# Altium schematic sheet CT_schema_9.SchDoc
size 254 x 194 mm
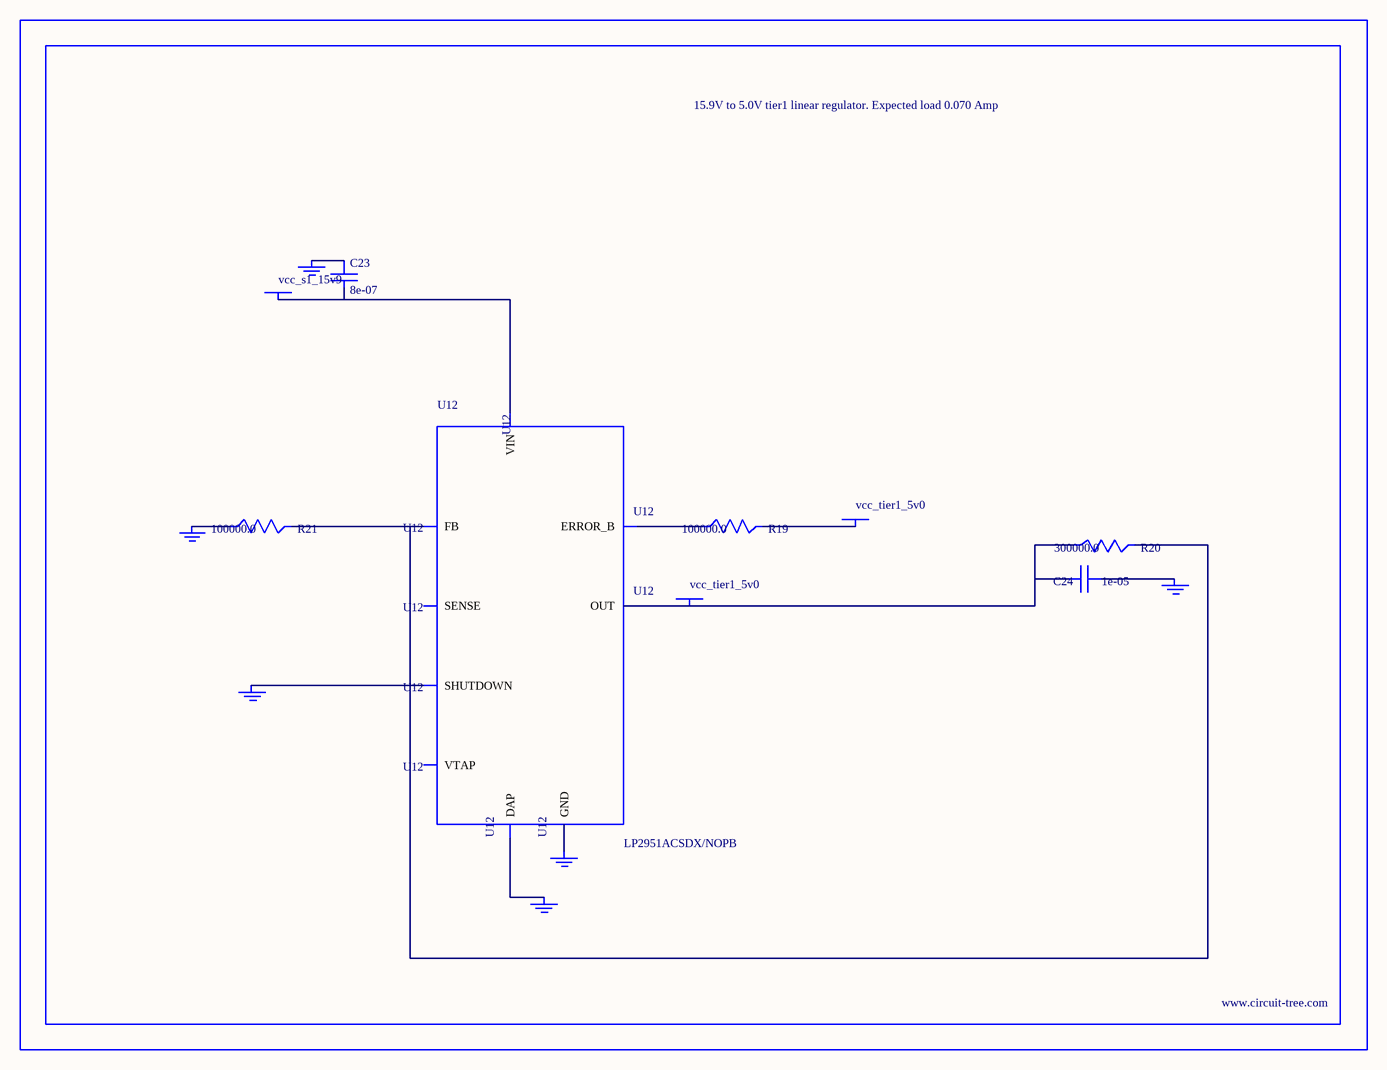
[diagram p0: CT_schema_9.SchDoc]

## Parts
BORDER8  (no value)
C23  8e-07  [R0603]
C24  1e-05  [C1210]
GND_INSTANCE_8_0  (no value)
GND_INSTANCE_8_1  (no value)
GND_INSTANCE_8_2  (no value)
GND_INSTANCE_8_3  (no value)
GND_INSTANCE_8_4  (no value)
GND_INSTANCE_8_5  (no value)
POWER_INSTANCE_8_0  vcc_tier1_5v0
POWER_INSTANCE_8_1  vcc_s1_15v9
POWER_INSTANCE_8_2  vcc_tier1_5v0
R19  100000.0  [R0603]
R20  300000.0  [R0603]
R21  100000.0  [R0603]
U12  LP2951ACSDX/NOPB  [WSON-8]

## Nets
NetC23_1: C23.1 GND_INSTANCE_8_3.0(GND)
NetC23_2: C23.2 POWER_INSTANCE_8_1.0(PWR) U12.8(VIN)
NetC24_1: C24.1 GND_INSTANCE_8_0.0(GND)
NetC24_2: C24.2 POWER_INSTANCE_8_2.0(PWR) R20.1 U12.1(OUT)
NetGND_INSTANCE_8_1_0: GND_INSTANCE_8_1.0(GND) U12.3(SHUTDOWN)
NetGND_INSTANCE_8_2_0: GND_INSTANCE_8_2.0(GND) R21.1
NetGND_INSTANCE_8_4_0: GND_INSTANCE_8_4.0(GND) U12.PAD(DAP)
NetGND_INSTANCE_8_5_0: GND_INSTANCE_8_5.0(GND) U12.4(GND)
NetPOWER_INSTANCE_8_0_0: POWER_INSTANCE_8_0.0(PWR) R19.2
NetR19_1: R19.1 U12.5(ERROR_B)
NetR20_2: R20.2 R21.2 U12.7(FB)

Not connected (* = marked no-connect by the designer): U12 2(SENSE) 6(VTAP)

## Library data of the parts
BORDER8 = BORDER_PAGE8
C23 = C23
C24 = GRM32DR61E106MA12L
GND_INSTANCE_8_0-GND_INSTANCE_8_5 = GND
POWER_INSTANCE_8_0-POWER_INSTANCE_8_2 = PWR
R19 R21 = RC0603JR-07100KL
R20 = RC0603JR-07300KL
